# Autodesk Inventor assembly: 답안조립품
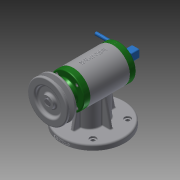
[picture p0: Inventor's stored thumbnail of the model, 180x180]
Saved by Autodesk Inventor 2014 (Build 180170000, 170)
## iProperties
Created: 2017-02
Part Number: 답안조립품
Document SubType Name: Assembly
Designer: owner
Author: owner
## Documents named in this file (16)
- C:\Users\owner\Desktop\370207V1002\답안조립품.iam
- C:\Users\owner\Desktop\370207V1002\본체.ipt
- C:\Users\owner\Desktop\370207V1002\V벨트풀리.ipt
- C:\Users\owner\Desktop\370207V1002\뒤커버.ipt
- C:\Users\owner\Desktop\370207V1002\레버.ipt
- C:\Users\owner\Desktop\370207V1002\멈춤나사 M3x8.ipt
- C:\Users\owner\Desktop\370207V1002\베어링 6201.ipt
- C:\Users\owner\Desktop\370207V1002\베어링 6202.ipt
- C:\Users\owner\Desktop\370207V1002\본체상부커버.ipt
- C:\Users\owner\Desktop\370207V1002\볼트 M3x0.5x8.ipt
- C:\Users\owner\Desktop\370207V1002\슬라이드.ipt
- C:\Users\owner\Desktop\370207V1002\앞커버.ipt
- C:\Users\owner\Desktop\370207V1002\오일실 12 22 7.ipt
- C:\Users\owner\Desktop\370207V1002\키 4 x 4 x 18.ipt
- C:\Users\owner\Desktop\370207V1002\편심축.ipt
- C:\Users\owner\Desktop\370207V1002\가변스프링.ipt
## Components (2 placed, 2 different names)
1. V벨트풀리:1 — 각도:2
2. 가변스프링:1
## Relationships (1: Angle 1)
- 각도:2 [Angle]: V벨트풀리:1
